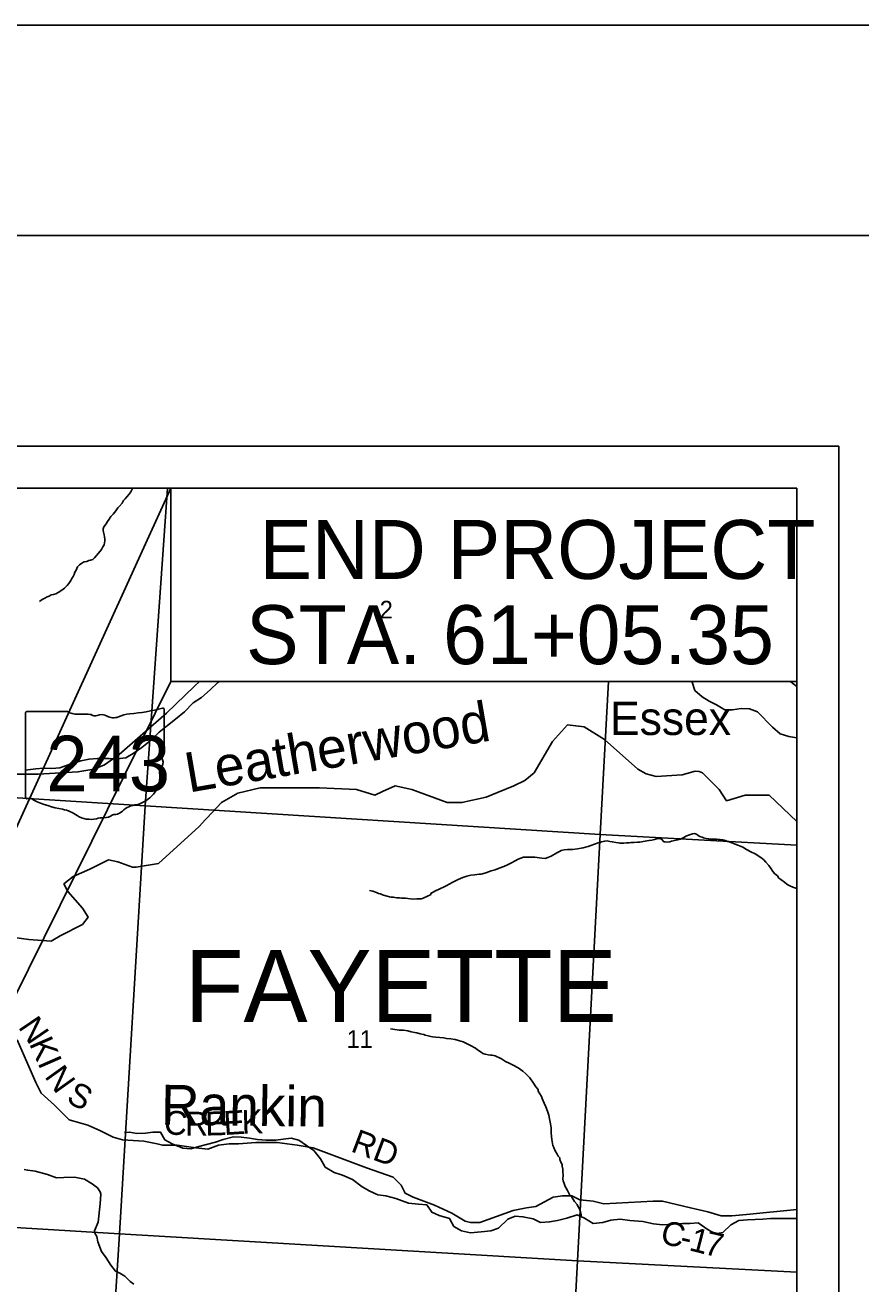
# Model space of a CAD drawing. Extents: x 0 to 45.4, y -2.2 to 22.
# Drawn here: x 7.067 to 9.052, y 19.01 to 22 of the extents above; entities that cross this region are included whole.
import ezdxf

# ---------------------------------------------------------------- set-up
doc = ezdxf.new("R2010")
doc.units = 0
for name, color, linetype in [('GM_X_Corporation', 7, 'Continuous'), ('GM_X_County_Road', 7, 'Continuous'), ('GM_X_County_Road_Text', 7, 'Continuous'), ('GM_X_Minor_River', 7, 'Continuous'), ('GM_X_Minor_River_Text', 7, 'Continuous'), ('GM_X_Section_Text', 7, 'Continuous'), ('GM_X_State_Location', 7, 'Continuous'), ('GM_X_State_Route', 7, 'Continuous'), ('GM_X_State_Shield', 7, 'Continuous'), ('GM_X_Township_Road', 7, 'Continuous'), ('GM_X_Township_Text', 7, 'Continuous'), ('GM_X_Unincorporated_Text', 7, 'Continuous'), ('SH_Border', 7, 'Continuous'), ('SH_Cut_Line', 7, 'Continuous'), ('SH_Data', 7, 'Continuous'), ('SH_Text', 7, 'Continuous')]:
    doc.layers.add(name, color=color, linetype=linetype)

msp = doc.modelspace()

# ---------------------------------------------------------------- linework, layer by layer
at = {"layer": 'GM_X_Corporation'}
for points in [[(5.6021, 14.1), (7.0413, 14.1), (7.1146, 14.1136), (7.5608, 14.2194), (7.6244, 14.2444), (8.0832, 14.3972), (8.4711, 14.5406), (8.5907, 14.5823), (8.8228, 14.6772), (8.9, 14.7192), (8.9, 20.9), (2.1, 20.9)], [(5.6021, 14.1), (7.0413, 14.1), (7.1146, 14.1136), (7.5608, 14.2194), (7.6244, 14.2444), (8.0832, 14.3972), (8.4711, 14.5406), (8.5907, 14.5823), (8.8228, 14.6772), (8.9, 14.7192), (8.9, 20.9), (6.2942, 20.9), (6.2882, 20.8226), (6.2789, 20.7002), (6.2588, 20.2929), (6.2538, 20.2076), (6.2346, 20.0088), (6.2236, 19.8542), (6.181, 19.2539), (6.1763, 19.1885), (6.1061, 18.1607), (5.642, 18.1908)], [(8.4774, 20.9), (7.4048, 20.9), (7.3518, 20.1452), (8.4327, 20.0771), (8.4525, 20.4406)], [(8.4525, 20.4406), (8.4327, 20.0771), (8.9, 20.0521), (8.9, 20.9), (8.4774, 20.9)]]:
    msp.add_lwpolyline(points, dxfattribs=at)
for points in [[(7.4048, 20.9), (6.3012, 20.9), (6.2516, 20.2138), (7.3518, 20.1452)], [(6.2516, 20.2138), (7.3518, 20.1452), (7.2905, 19.1287), (6.1827, 19.1954)], [(7.3518, 20.1452), (8.4327, 20.0771), (8.3794, 19.064), (7.2905, 19.1287)], [(8.9, 19.0371), (8.9, 20.0521), (8.4327, 20.0771), (8.3794, 19.064)], [(7.2905, 19.1287), (7.2262, 18.1039), (6.1142, 18.166), (6.1827, 19.1954)], [(8.3794, 19.064), (8.3245, 18.0384), (7.2262, 18.1039), (7.2905, 19.1287)], [(8.9, 18.0073), (8.9, 19.0371), (8.3794, 19.064), (8.3245, 18.0384)]]:
    msp.add_lwpolyline(points, close=True, dxfattribs=at)
at = {"layer": 'GM_X_County_Road'}
msp.add_lwpolyline([(7.0476, 19.5892), (7.092, 19.4879), (7.1047, 19.4625), (7.1364, 19.434), (7.1554, 19.415), (7.1712, 19.3992), (7.2156, 19.3865), (7.2441, 19.3738), (7.2758, 19.358), (7.298, 19.3516), (7.3487, 19.3485), (7.3803, 19.3421), (7.393, 19.339), (7.4279, 19.339), (7.4722, 19.3326), (7.5008, 19.3295), (7.5261, 19.339), (7.5514, 19.3421), (7.5736, 19.3421), (7.6148, 19.3453), (7.6655, 19.3453), (7.7131, 19.3389), (7.7511, 19.3326), (7.8778, 19.2851), (7.9412, 19.2629), (7.9602, 19.2439), (7.9697, 19.2249), (7.9888, 19.2154), (8.0394, 19.1964), (8.0806, 19.1774), (8.1123, 19.1584), (8.125, 19.1552), (8.1472, 19.1552), (8.2264, 19.1837), (8.2581, 19.19), (8.2803, 19.1932), (8.3215, 19.2154), (8.3436, 19.2185), (8.3658, 19.2185), (8.3848, 19.209), (8.4165, 19.2058), (8.4419, 19.1995), (8.5591, 19.2058), (8.5813, 19.2058), (8.6478, 19.19), (8.689, 19.1805), (8.7207, 19.171), (8.7461, 19.171), (8.7809, 19.1741), (8.9, 19.1864)], dxfattribs=at)
at = {"layer": 'GM_X_Minor_River'}
for points in [[(7.3231, 20.9), (7.321, 20.8974), (7.3179, 20.8913), (7.3136, 20.8861), (7.3086, 20.8797), (7.3039, 20.8745), (7.3001, 20.8704), (7.2969, 20.8644), (7.2911, 20.8576), (7.2865, 20.8535), (7.2822, 20.8464), (7.276, 20.8385), (7.2706, 20.8325), (7.266, 20.8262), (7.2621, 20.8205), (7.259, 20.8153), (7.2539, 20.8081), (7.2523, 20.8036), (7.2522, 20.7994), (7.2529, 20.7952), (7.2543, 20.7888), (7.255, 20.7846), (7.2557, 20.7792)], [(7.2557, 20.7792), (7.256, 20.7747), (7.2555, 20.7698), (7.2547, 20.7656), (7.2512, 20.7607), (7.2477, 20.7539), (7.2411, 20.7453), (7.236, 20.7397), (7.2314, 20.7345), (7.2272, 20.7308), (7.2222, 20.7289), (7.218, 20.7282), (7.2131, 20.7261), (7.2066, 20.7246), (7.2013, 20.7217), (7.1959, 20.7176), (7.1913, 20.7135), (7.1877, 20.7052), (7.185, 20.7003), (7.1834, 20.6947), (7.1806, 20.6898), (7.1775, 20.6853), (7.1752, 20.6808), (7.1701, 20.6736), (7.1666, 20.6684), (7.1604, 20.6624), (7.1535, 20.6576), (7.1447, 20.652), (7.1394, 20.6487), (7.1337, 20.6477), (7.1287, 20.6462), (7.1237, 20.6437), (7.1192, 20.6418), (7.1138, 20.6389), (7.1088, 20.6363), (7.1046, 20.6337), (7.1004, 20.6304)], [(7.5274, 20.4406), (7.5246, 20.438), (7.5063, 20.4206), (7.4858, 20.4025), (7.4661, 20.3897), (7.4455, 20.3685), (7.4235, 20.3511), (7.4052, 20.336), (7.3847, 20.3201), (7.3634, 20.2997), (7.3437, 20.2838), (7.3232, 20.2695), (7.3057, 20.2597), (7.2852, 20.2567), (7.2663, 20.2575), (7.2383, 20.2577), (7.2186, 20.2562), (7.1989, 20.2525), (7.1739, 20.2442), (7.1488, 20.2352), (7.1299, 20.2338), (7.1102, 20.2346), (7.092, 20.2331), (7.0663, 20.2302)], [(8.9, 20.3067), (8.8812, 20.31), (8.8608, 20.3162), (8.8427, 20.3322), (8.8065, 20.3688), (8.7876, 20.3757), (8.7679, 20.3765), (8.7474, 20.3735), (8.7293, 20.3736), (8.7096, 20.3851), (8.6922, 20.3942), (8.6749, 20.4042), (8.6575, 20.4194), (8.6515, 20.4392), (8.6512, 20.4406)], [(8.9, 19.9476), (8.8981, 19.9493), (8.891, 19.9521), (8.8839, 19.9549), (8.8801, 19.9565), (8.8764, 19.9592), (8.8708, 19.9639), (8.8625, 19.9701), (8.8573, 19.9736), (8.854, 19.9786), (8.848, 19.9836), (8.8432, 19.989), (8.8391, 19.9955), (8.8336, 20.0032), (8.8265, 20.0113), (8.8217, 20.0167), (8.818, 20.0202), (8.8097, 20.026), (8.8015, 20.0311), (8.791, 20.0362), (8.7805, 20.0417), (8.7715, 20.0468), (8.7598, 20.0519), (8.7497, 20.0559), (8.7421, 20.0587), (8.7357, 20.0607), (8.732, 20.0619), (8.7274, 20.0635), (8.7241, 20.0643), (8.718, 20.0652), (8.7135, 20.0656), (8.7093, 20.0661), (8.7032, 20.0658), (8.6979, 20.0663), (8.6945, 20.0663), (8.6904, 20.0672), (8.6851, 20.0676), (8.6787, 20.0693), (8.6749, 20.0709), (8.67, 20.0728), (8.6659, 20.0752), (8.6618, 20.0783), (8.6569, 20.0795), (8.652, 20.0788), (8.6451, 20.0763), (8.6367, 20.073), (8.6329, 20.0708), (8.6283, 20.0686), (8.6241, 20.0664), (8.6172, 20.0642), (8.6134, 20.0635), (8.6066, 20.0621), (8.602, 20.0611), (8.5982, 20.06), (8.5925, 20.0593), (8.5872, 20.0594), (8.5838, 20.0599), (8.5805, 20.0649), (8.5771, 20.0672), (8.573, 20.0673), (8.5677, 20.0666), (8.562, 20.0656), (8.5559, 20.0641), (8.5487, 20.0627), (8.5266, 20.0586), (8.5217, 20.0587), (8.513, 20.058), (8.5058, 20.0578), (8.502, 20.0575), (8.4955, 20.0572), (8.4891, 20.0565), (8.4845, 20.0562), (8.48, 20.0567), (8.4766, 20.0571), (8.4705, 20.058), (8.4615, 20.0601), (8.4558, 20.0609), (8.4498, 20.0618), (8.4437, 20.0615), (8.4361, 20.0597), (8.4281, 20.0576), (8.411, 20.051), (8.4045, 20.0485), (8.3984, 20.0467), (8.3923, 20.0453), (8.3877, 20.0446), (8.3794, 20.0432), (8.3668, 20.0415), (8.3555, 20.0414), (8.3475, 20.0407), (8.3437, 20.04), (8.3399, 20.039), (8.3361, 20.0371), (8.3296, 20.0334), (8.3162, 20.0257), (8.3089, 20.0224), (8.3025, 20.0202), (8.2945, 20.0211), (8.2775, 20.0233), (8.2574, 20.0233)], [(8.2574, 20.0233), (8.251, 20.023), (8.2441, 20.0212), (8.238, 20.0187), (8.2312, 20.015), (8.2224, 20.0098), (8.2189, 20.008), (8.2128, 20.0051), (8.2044, 20.0014), (8.193, 19.997), (8.1838, 19.9934), (8.1743, 19.9905), (8.1613, 19.9862), (8.1537, 19.984), (8.1503, 19.9833), (8.1457, 19.9827), (8.1397, 19.982), (8.1351, 19.9813), (8.1256, 19.9803), (8.1161, 19.9782), (8.1066, 19.9754), (8.0952, 19.9706), (8.0829, 19.9636), (8.0745, 19.9592), (8.0684, 19.9563), (8.0619, 19.9529), (8.052, 19.9482), (8.0401, 19.9427), (8.0359, 19.9405), (8.0317, 19.9379), (8.0294, 19.9338), (8.0225, 19.9308), (8.0126, 19.9261), (8.0084, 19.9246), (8.0023, 19.9243), (7.9974, 19.9241), (7.9875, 19.9238), (7.9762, 19.9248), (7.9701, 19.9257), (7.9652, 19.9257), (7.9607, 19.9262), (7.9565, 19.9266), (7.9501, 19.9271), (7.9452, 19.9276), (7.9418, 19.928), (7.9365, 19.9285), (7.9323, 19.9293), (7.9267, 19.9306), (7.9233, 19.9314), (7.9154, 19.9342), (7.9108, 19.9362), (7.9063, 19.9374), (7.9011, 19.9394), (7.8924, 19.9422), (7.8848, 19.9438)], [(8.3878, 19.1685), (8.3879, 19.1735), (8.3862, 19.1811), (8.3843, 19.1853), (8.3829, 19.1891), (8.3796, 19.1941), (8.3785, 19.1983), (8.3722, 19.2052), (8.3652, 19.2152), (8.3611, 19.2206), (8.3556, 19.231), (8.3519, 19.2367), (8.3497, 19.2409), (8.3472, 19.2482), (8.3447, 19.2547), (8.3443, 19.2581), (8.3449, 19.2676), (8.3443, 19.276), (8.344, 19.2817), (8.3426, 19.2889), (8.3423, 19.2931), (8.3398, 19.2984), (8.3372, 19.3053), (8.3369, 19.3087), (8.3332, 19.313), (8.3306, 19.3176), (8.3255, 19.3272), (8.3226, 19.3333), (8.3208, 19.3383), (8.3187, 19.3478), (8.3184, 19.3523), (8.317, 19.36), (8.3164, 19.3687), (8.3166, 19.3805), (8.3152, 19.39), (8.3128, 19.4018), (8.311, 19.4102), (8.3078, 19.4197), (8.3038, 19.4301), (8.3002, 19.4385), (8.2947, 19.4503), (8.2937, 19.4549), (8.2859, 19.4672), (8.2852, 19.4714), (8.2797, 19.4779), (8.2741, 19.4864), (8.2656, 19.4987), (8.2563, 19.5087), (8.2493, 19.5149), (8.2436, 19.5188), (8.2384, 19.5227), (8.2264, 19.529), (8.2166, 19.5337), (8.2076, 19.5376), (8.1986, 19.5439), (8.1934, 19.5462), (8.1866, 19.5498), (8.1832, 19.551), (8.1798, 19.5522), (8.1764, 19.5526), (8.1727, 19.553), (8.1666, 19.5539), (8.1598, 19.5551), (8.1542, 19.5571), (8.1501, 19.5599), (8.1418, 19.5657), (8.1366, 19.5692), (8.1332, 19.5712), (8.1276, 19.5743), (8.1186, 19.5794), (8.1073, 19.5849), (8.096, 19.5878), (8.0881, 19.5898), (8.0779, 19.5915), (8.0677, 19.5928), (8.0613, 19.594), (8.0518, 19.595), (8.0427, 19.5959), (8.0348, 19.5968), (8.0307, 19.5976), (8.0246, 19.5988), (8.0171, 19.6005), (8.0137, 19.6017), (8.005, 19.6037), (7.9975, 19.6058), (7.9922, 19.607), (7.9839, 19.6086), (7.9756, 19.6107), (7.9654, 19.612), (7.9555, 19.6122), (7.9404, 19.6147), (7.9344, 19.6152)], [(8.9, 19.1644), (8.8991, 19.1645), (8.8378, 19.1647), (8.8196, 19.1633), (8.7832, 19.1619), (8.762, 19.1604), (8.743, 19.1499), (8.724, 19.1317), (8.7066, 19.1288), (8.6892, 19.1379), (8.6658, 19.1547), (8.6461, 19.1533), (8.6287, 19.1533), (8.6067, 19.1511), (8.581, 19.1497), (8.5598, 19.1521), (8.534, 19.1575), (8.503, 19.1599), (8.4803, 19.163), (8.4583, 19.1608), (8.4394, 19.1556), (8.4166, 19.1526), (8.3955, 19.1656), (8.3781, 19.1732), (8.3538, 19.1657), (8.3318, 19.1605), (8.3129, 19.1568), (8.2909, 19.1554), (8.2735, 19.1638), (8.2493, 19.1692), (8.2312, 19.1708), (8.2137, 19.1632), (8.1916, 19.1421), (8.1734, 19.1353), (8.15, 19.1331), (8.125, 19.1309), (8.1038, 19.1355), (8.0849, 19.1462), (8.0751, 19.1645), (8.0501, 19.1722), (8.0328, 19.1798), (8.0207, 19.1973), (8.001, 19.1989), (7.9776, 19.2013), (7.9473, 19.212), (7.9239, 19.219), (7.9049, 19.2213), (7.8853, 19.2297), (7.8672, 19.2404), (7.8445, 19.2572), (7.8203, 19.2679), (7.8007, 19.2741), (7.7795, 19.287), (7.7682, 19.3068), (7.7524, 19.3266), (7.735, 19.3381), (7.7169, 19.351), (7.6988, 19.3557), (7.6798, 19.3535), (7.6624, 19.3512), (7.6397, 19.3506), (7.6185, 19.3529), (7.5995, 19.356), (7.5799, 19.3584), (7.5617, 19.3592), (7.5374, 19.3525), (7.5192, 19.3465), (7.4972, 19.3405), (7.479, 19.336), (7.4601, 19.3307), (7.4411, 19.3316), (7.4162, 19.3423), (7.3988, 19.3514), (7.3883, 19.3697), (7.3701, 19.3698), (7.3527, 19.3676), (7.3322, 19.3669), (7.3148, 19.37), (7.3027, 19.3693)]]:
    msp.add_lwpolyline(points, dxfattribs=at)
at = {"layer": 'GM_X_State_Route'}
for points in [[(7.044, 20.2207), (7.0977, 20.2206), (7.192, 20.226), (7.2299, 20.2324), (7.2553, 20.2425), (7.2898, 20.2675), (7.4026, 20.3658), (7.4694, 20.4298), (7.4809, 20.4406)], [(8.8853, 20.4406), (8.8896, 20.4371), (8.9, 20.4287)]]:
    msp.add_lwpolyline(points, dxfattribs=at)
at = {"layer": 'GM_X_State_Shield'}
for p, q in [((7.0674, 20.3659), (7.0674, 20.1658)), ((7.1672, 20.3693), (7.0707, 20.3693)), ((7.397, 20.2696), (7.397, 20.3743)), ((7.397, 20.2696), (7.397, 20.2696))]:
    msp.add_line(p, q, dxfattribs=at)
for centre, major_axis, start_param, end_param in [((7.0712, 20.3663), (0.00382, 0), 1.712693, 3.28349), ((7.1902, 20.3925), (0.037, 0), 4.042523, 4.731795), ((7.2796, 20.6421), (0.3495, 0), 4.814394, 5.042369), ((7.3934, 20.3747), (0.00367, 0), 6.141152, 7.989035), ((7.2025, 20.257), (0.133, 0), 1.404758, 1.657858), ((7.2327, 20.3673), (0.0107, 0), 3.836095, 5.185415), ((7.2483, 20.3442), (0.0222, 0), 0.950623, 2.079405), ((7.277, 20.3759), (0.0267, 0), 4.081561, 5.145723), ((7.3242, 20.3082), (0.0703, 0), 1.699011, 2.107814), ((7.3962, 20.2619), (0.00568, 0), 1.883978, 3.671073), ((7.3601, 20.2487), (0.0341, 0), 5.934695, 6.695948), ((7.3931, 20.2692), (0.00393, 0), 5.05454, 6.418171), ((7.2992, 20.2125), (0.0874, 0), 5.101752, 6.440018), ((7.4102, 20.2258), (0.0248, 0), 2.387724, 3.262537), ((7.0713, 20.1653), (0.00385, 0), 3.00124, 4.508301), ((7.0718, 20.1858), (0.0294, 0), 4.665946, 4.897461), ((7.0778, 20.1542), (0.0106, 0), 0.519207, 1.627899), ((7.2117, 20.334), (0.2524, 0), 4.195997, 4.488961), ((7.1364, 20.0758), (0.079, 0), 0.823519, 1.323587), ((7.2786, 20.1188), (0.00752, 0), 1.147584, 2.315152), ((7.2754, 20.1464), (0.0282, 0), 4.937069, 5.64225), ((7.3361, 20.1096), (0.0479, 0), 1.647645, 2.488434), ((7.2218, 20.1532), (0.0501, 0), 4.026481, 4.996735), ((7.2508, 20.084), (0.0412, 0), 1.495662, 1.94098), ((7.2545, 20.1382), (0.0267, 0), 4.691044, 5.507374)]:
    msp.add_ellipse(centre, major_axis=major_axis, ratio=0.8, start_param=start_param, end_param=end_param, dxfattribs=at)
at = {"layer": 'GM_X_Township_Road'}
for points in [[(7.4987, 20.1162), (7.5328, 20.1531), (7.5723, 20.1751), (7.6251, 20.1883), (7.7658, 20.1883), (7.8538, 20.1839), (7.8978, 20.1707), (7.9154, 20.1795), (7.9462, 20.1926), (7.9857, 20.1838), (8.0693, 20.1531), (8.1045, 20.1531), (8.1617, 20.1662), (8.1893, 20.1773), (8.2276, 20.1926), (8.254, 20.2058), (8.276, 20.2234), (8.32, 20.2981), (8.3552, 20.3377), (8.3947, 20.3333), (8.4431, 20.3025), (8.5223, 20.2322), (8.5421, 20.2217), (8.5663, 20.2146), (8.6278, 20.219), (8.6586, 20.2278), (8.668, 20.2272), (8.6762, 20.2234), (8.7158, 20.1838), (8.7334, 20.1574), (8.7774, 20.1706), (8.8345, 20.1706), (8.9, 20.1079)], [(6.8207, 19.6792), (6.9258, 19.7487), (7.0094, 19.8102), (7.0402, 19.8322), (7.0754, 19.8278), (7.1281, 19.8234), (7.1501, 19.8366), (7.2029, 19.863), (7.2161, 19.8806), (7.2029, 19.9025), (7.1677, 19.9421), (7.1589, 19.9597), (7.1809, 19.9773), (7.2205, 19.9949), (7.2381, 20.0037), (7.2645, 20.0168), (7.2865, 20.0124), (7.3216, 19.9993), (7.3304, 19.9993), (7.3832, 20.008), (7.48, 20.096), (7.4954, 20.1127), (7.4987, 20.1162)], [(7.3246, 19.0091), (7.3164, 19.0153), (7.3036, 19.0278), (7.2918, 19.0346), (7.2813, 19.04), (7.2699, 19.0538), (7.2594, 19.0712), (7.2479, 19.0866), (7.2397, 19.1091), (7.2372, 19.1218), (7.2316, 19.1315), (7.2312, 19.1359), (7.2402, 19.1563), (7.245, 19.2), (7.2461, 19.2227), (7.2445, 19.2284), (7.2382, 19.2379), (7.2262, 19.2471), (7.2077, 19.2583), (7.1837, 19.2627), (7.1582, 19.2619), (7.141, 19.2616), (7.1199, 19.2693), (7.0907, 19.2774), (7.0728, 19.2795), (7.0646, 19.2813)]]:
    msp.add_lwpolyline(points, dxfattribs=at)
at = {"layer": 'SH_Border'}
msp.add_lwpolyline([(1.5, 21.5), (33.5, 21.5), (33.5, 0.5), (1.5, 0.5)], close=True, dxfattribs=at)
at = {"layer": 'SH_Cut_Line'}
msp.add_lwpolyline([(0, 0), (34, 0), (34, 22), (0, 22)], close=True, dxfattribs=at)
at = {"layer": 'SH_Data'}
for p, q in [((2, 21), (9, 21)), ((9, 21), (9, 14)), ((2.1, 20.9), (8.9, 20.9)), ((8.9, 20.9), (8.9, 14.1))]:
    msp.add_line(p, q, dxfattribs=at)
at = {"layer": 'SH_Text'}
for points in [[(7.4129, 20.9), (4.8173, 15.1976), (7.4129, 20.4406)], [(8.9, 20.9), (7.4129, 20.9), (7.4129, 20.4406), (8.9, 20.4406)]]:
    msp.add_lwpolyline(points, close=True, dxfattribs=at)

# ---------------------------------------------------------------- texts
at = {"layer": 'GM_X_County_Road_Text'}
for s, height, rotation, p in [('N', 0.0568, 304.025, (7.0488, 19.6198)), ('K', 0.0568, 293.6398, (7.0754, 19.5808)), ('I', 0.0568, 293.5955, (7.0955, 19.535)), ('N', 0.0568, 305.5773, (7.1112, 19.5023)), ('S', 0.0568, 332.127, (7.1618, 19.4429)), ('C', 0.0568, 354.6277, (7.3945, 19.3664)), ('R', 0.0568, 359.9039, (7.4466, 19.3617)), ('E', 0.0568, 1.6911, (7.4953, 19.3617)), ('E', 0.0568, 3.7194, (7.5399, 19.363)), ('K', 0.0568, 1.9164, (7.5819, 19.3658)), ('RD', 0.05682, 339.3866, (7.8379, 19.3252)), ('C', 0.0568, 345.0772, (8.5728, 19.1077)), ('1', 0.0568, 345.5731, (8.6418, 19.0899)), ('-', 0.0568, 346.4803, (8.6194, 19.0953)), ('7', 0.0568, 346.8992, (8.6771, 19.0809))]:
    msp.add_text(s, height=height, rotation=rotation, dxfattribs=at).set_placement(p)
at = {"layer": 'GM_X_Minor_River_Text'}
for s, height, rotation, p in [('Leatherwood', 0.094691, 9.7799, (7.4552, 20.1765)), ('Rankin', 0.09469, 359.2425, (7.3889, 19.388))]:
    msp.add_text(s, height=height, rotation=rotation, dxfattribs=at).set_placement(p)
at = {"layer": 'GM_X_Section_Text'}
for s, height, p in [('2', 0.0419, (7.9092, 20.5905)), ('11', 0.04186, (7.8304, 19.5702))]:
    msp.add_text(s, height=height, rotation=0, dxfattribs=at).set_placement(p)
at = {"layer": 'GM_X_State_Location'}
for s in ['s', 'r']:
    msp.add_text(s, height=0.000189, dxfattribs=at).set_placement((7.2285, 20.2525))
msp.add_text('243', height=0.000189, rotation=0, dxfattribs=at).set_placement((7.1617, 20.2387))
at = {"layer": 'GM_X_State_Shield'}
msp.add_text('243', height=0.13184, dxfattribs=at).set_placement((7.1169, 20.1799))
at = {"layer": 'GM_X_Township_Text'}
msp.add_text('FAYETTE', height=0.17045, rotation=0, dxfattribs=at).set_placement((7.4463, 19.6321))
at = {"layer": 'GM_X_Unincorporated_Text'}
msp.add_text('Essex', height=0.07898, rotation=0, dxfattribs=at).set_placement((8.4563, 20.3136))
at = {"layer": 'SH_Text'}
for s, p in [('END PROJECT', (7.6233, 20.6844)), ('STA. 61+05.35', (7.5915, 20.4819))]:
    msp.add_text(s, height=0.14, dxfattribs=at).set_placement(p)

doc.saveas('drawing.dxf')
